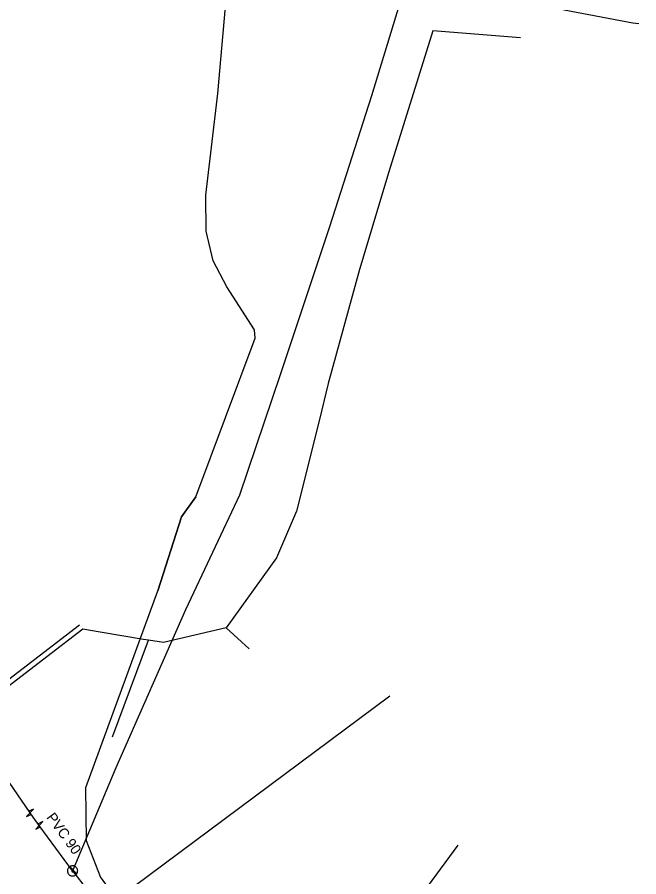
# Model space of a CAD drawing. Extents: x -743072 to -742584, y -978827 to -978325.
# Drawn here: x -742806.2 to -742745.4, y -978569.2 to -978485.2 of the extents above; entities that cross this region are included whole.
import ezdxf

# ---------------------------------------------------------------- set-up
doc = ezdxf.new("R2010")
doc.units = 0
for name, color, linetype in [('IS_CETIN_sdělovací kabel_nadz', 7, 'Continuous'), ('IS_CETIN_sdělovací kabel_optika', 7, 'Continuous'), ('IS_Obec_kabel VO_nadz', 7, 'Continuous'), ('IS_popis_ScVK', 7, 'Continuous'), ('IS_ScVK_Kanal_dest', 7, 'Continuous'), ('IS_ScVK_Vodovod', 7, 'Continuous')]:
    doc.layers.add(name, color=color, linetype=linetype)

msp = doc.modelspace()

# ---------------------------------------------------------------- linework, layer by layer
at = {"layer": 'IS_CETIN_sdělovací kabel_nadz'}
msp.add_lwpolyline([(-742799.79, -978544.98), (-742828.86, -978567.32), (-742867.05, -978521.91), (-742897.64, -978486.54), (-742872.63, -978477.97), (-742862.09, -978471.14)], dxfattribs=at)
at = {"layer": 'IS_CETIN_sdělovací kabel_optika'}
for points in [[(-742790.25, -978579.9), (-742798.06, -978569.19), (-742799.43, -978565.66), (-742799.48, -978560.47), (-742792.46, -978541.24), (-742790.14, -978534), (-742788.73, -978532.06), (-742782.94, -978516.55), (-742783.01, -978515.73), (-742785.72, -978511.53), (-742787.03, -978508.97), (-742787.73, -978506.08), (-742787.75, -978502.56), (-742786.58, -978492.63), (-742785.55, -978480.8), (-742785.2, -978469.35), (-742786.17, -978454.14), (-742787.96, -978447.91), (-742788.08, -978439.4), (-742787.761, -978434.797)], [(-742757.01, -978487.16), (-742765.58, -978486.5), (-742769.87, -978500.27), (-742772.73, -978509.81), (-742775.79, -978520.96), (-742776.67, -978524.61), (-742778.91, -978533.46), (-742780.85, -978538.01), (-742785.76, -978544.86)], [(-742788.73, -978532.06), (-742790.14, -978534), (-742792.46, -978541.24)], [(-742780.85, -978538.01), (-742785.76, -978544.86)], [(-742793.35, -978546.06), (-742793.85, -978545.98), (-742798.09, -978545.27), (-742799.79, -978544.98)], [(-742785.76, -978544.86), (-742791.88, -978546.3), (-742793.35, -978546.06)], [(-742785.76, -978544.86), (-742783.53, -978546.89)], [(-742793.85, -978545.98), (-742798.09, -978545.27)], [(-742796.87, -978555.51), (-742793.35, -978546.06)]]:
    msp.add_lwpolyline(points, dxfattribs=at)
at = {"layer": 'IS_Obec_kabel VO_nadz'}
msp.add_lwpolyline([(-742800.095, -978544.584), (-742828.785, -978566.632), (-742866.67, -978521.586), (-742896.777, -978486.773), (-742872.41, -978478.423), (-742861.818, -978471.56)], dxfattribs=at)
at = {"layer": 'IS_ScVK_Kanal_dest'}
for points in [[(-742763.132, -978566.086), (-742780.82, -978590.157)], [(-742800.73, -978568.5), (-742800.784, -978568.611)]]:
    msp.add_lwpolyline(points, dxfattribs=at)
at = {"layer": 'IS_ScVK_Vodovod'}
for points in [[(-742800.73, -978568.5), (-742796.53, -978558.52), (-742789.719, -978543.07), (-742784.42, -978531.86), (-742780.46, -978520.1), (-742775.64, -978505.609), (-742771.539, -978492.809), (-742767.87, -978480.82), (-742752.73, -978484.449), (-742746.028, -978485.692), (-742745.44, -978485.77)], [(-742804.943, -978562.941), (-742816.729, -978545.749)], [(-742797.699, -978572.3), (-742769.776, -978551.5)], [(-742805.299, -978563.304), (-742804.586, -978562.577)], [(-742804.586, -978562.577), (-742805.056, -978562.775)], [(-742805.299, -978563.304), (-742804.829, -978563.106)], [(-742804.031, -978564.16), (-742804.641, -978563.367), (-742804.943, -978562.941)], [(-742803.694, -978563.777), (-742804.367, -978564.542)], [(-742804.367, -978564.542), (-742803.908, -978564.319)], [(-742803.694, -978563.777), (-742804.153, -978564)], [(-742800.784, -978568.611), (-742804.031, -978564.16)], [(-742800.404, -978568.936), (-742800.372, -978568.894), (-742800.344, -978568.85), (-742800.323, -978568.803), (-742800.304, -978568.754), (-742800.292, -978568.702), (-742800.285, -978568.65), (-742800.284, -978568.598), (-742800.288, -978568.546), (-742800.297, -978568.495), (-742800.312, -978568.444), (-742800.332, -978568.396), (-742800.358, -978568.35), (-742800.386, -978568.307), (-742800.421, -978568.267), (-742800.458, -978568.231), (-742800.5, -978568.199), (-742800.544, -978568.171), (-742800.592, -978568.149), (-742800.64, -978568.131), (-742800.692, -978568.119), (-742800.744, -978568.112), (-742800.797, -978568.111), (-742800.849, -978568.115), (-742800.9, -978568.124), (-742800.95, -978568.139), (-742800.998, -978568.159), (-742801.045, -978568.184), (-742801.087, -978568.213), (-742801.127, -978568.248), (-742801.163, -978568.285), (-742801.195, -978568.327), (-742801.223, -978568.371), (-742801.246, -978568.419), (-742801.263, -978568.467), (-742801.275, -978568.519), (-742801.282, -978568.57), (-742801.284, -978568.623), (-742801.28, -978568.675), (-742801.27, -978568.727), (-742801.255, -978568.777), (-742801.235, -978568.825), (-742801.211, -978568.871), (-742801.181, -978568.914), (-742801.146, -978568.954), (-742801.109, -978568.99), (-742801.067, -978569.022), (-742801.023, -978569.05), (-742800.976, -978569.072), (-742800.927, -978569.09), (-742800.875, -978569.102), (-742800.824, -978569.109), (-742800.772, -978569.11), (-742800.72, -978569.106), (-742800.668, -978569.097), (-742800.617, -978569.082), (-742800.569, -978569.062), (-742800.524, -978569.037), (-742800.48, -978569.008), (-742800.44, -978568.973), (-742800.404, -978568.936)], [(-742801.077, -978568.14), (-742800.382, -978568.859)], [(-742800.721, -978568.664), (-742800.715, -978568.657), (-742800.712, -978568.65), (-742800.708, -978568.642), (-742800.705, -978568.634), (-742800.703, -978568.626), (-742800.702, -978568.617), (-742800.701, -978568.608), (-742800.702, -978568.6), (-742800.704, -978568.592), (-742800.706, -978568.583), (-742800.71, -978568.575), (-742800.714, -978568.568), (-742800.719, -978568.561), (-742800.723, -978568.554), (-742800.73, -978568.548), (-742800.737, -978568.542), (-742800.744, -978568.539), (-742800.752, -978568.535), (-742800.76, -978568.532), (-742800.768, -978568.53), (-742800.777, -978568.529), (-742800.786, -978568.528), (-742800.794, -978568.529), (-742800.803, -978568.53), (-742800.811, -978568.533), (-742800.819, -978568.537), (-742800.826, -978568.541), (-742800.833, -978568.546), (-742800.84, -978568.55), (-742800.846, -978568.557), (-742800.852, -978568.564), (-742800.855, -978568.571), (-742800.859, -978568.579), (-742800.862, -978568.587), (-742800.864, -978568.595), (-742800.866, -978568.603), (-742800.866, -978568.613), (-742800.865, -978568.621), (-742800.864, -978568.63), (-742800.861, -978568.638), (-742800.857, -978568.646), (-742800.853, -978568.653), (-742800.848, -978568.66), (-742800.844, -978568.667), (-742800.837, -978568.673), (-742800.83, -978568.679), (-742800.823, -978568.682), (-742800.815, -978568.686), (-742800.807, -978568.689), (-742800.799, -978568.691), (-742800.791, -978568.693), (-742800.781, -978568.693), (-742800.773, -978568.692), (-742800.765, -978568.69), (-742800.756, -978568.688), (-742800.748, -978568.684), (-742800.741, -978568.68), (-742800.734, -978568.675), (-742800.727, -978568.671), (-742800.721, -978568.664)], [(-742800.784, -978568.611), (-742797.865, -978572.386), (-742786.193, -978588.033), (-742785.215, -978589.035)]]:
    msp.add_lwpolyline(points, dxfattribs=at)

# ---------------------------------------------------------------- texts
at = {"layer": 'IS_popis_ScVK'}
msp.add_text('PVC 90', height=1, rotation=306, dxfattribs=at).set_placement((-742803.38, -978563.381))

doc.saveas('drawing.dxf')
